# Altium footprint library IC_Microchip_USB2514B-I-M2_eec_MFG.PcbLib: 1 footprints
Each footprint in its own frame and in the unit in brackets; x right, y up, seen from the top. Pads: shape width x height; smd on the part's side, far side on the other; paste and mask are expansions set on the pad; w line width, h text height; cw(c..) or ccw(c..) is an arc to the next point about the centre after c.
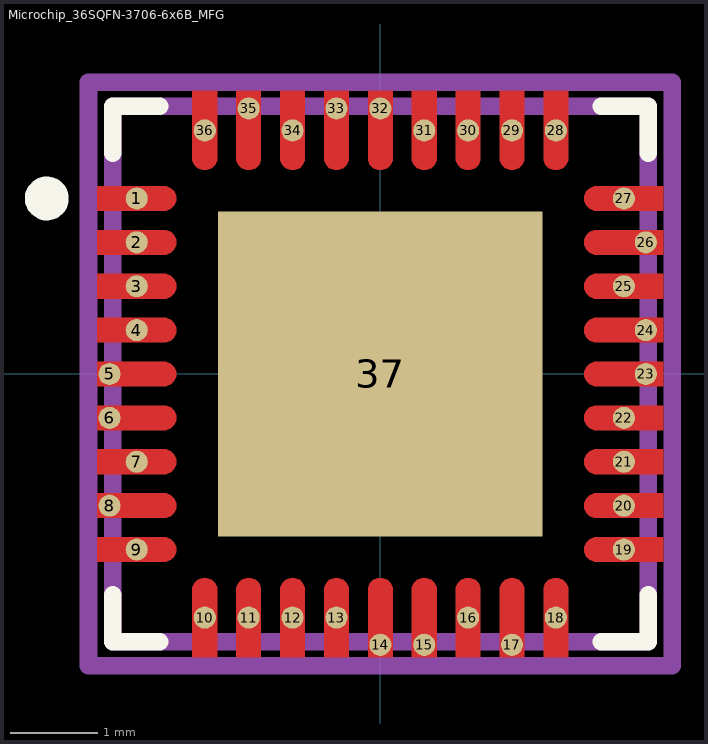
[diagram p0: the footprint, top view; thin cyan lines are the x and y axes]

## Microchip_36SQFN-3706-6x6B_MFG [mm]
pads (37):
  round 0.252 smd paste+0 mask+0: 1(-2.775,2) 2(-2.775,1.5) 3(-2.775,1) 4(-2.775,0.5) 5(-3.085,0) 6(-3.085,-0.5) 7(-2.775,-1) 8(-3.085,-1.5) 9(-2.775,-2) 10(-2,-2.775) 11(-1.5,-2.775) 12(-1,-2.775) 13(-0.5,-2.775) 14(0,-3.085) 15(0.5,-3.085) 16(1,-2.775) 17(1.5,-3.085) 18(2,-2.775) 19(2.775,-2) 20(2.775,-1.5) 21(2.775,-1) 22(2.775,-0.5) 23(3.025,0) 24(3.025,0.5) 25(2.775,1) 26(3.025,1.5) 27(2.775,2) 28(2,2.775) 29(1.5,2.775) 30(1,2.775) 31(0.5,2.775) 32(0,3.025) 33(-0.5,3.025) 34(-1,2.775) 35(-1.5,3.025) 36(-2,2.775)
  rect 3.7x3.7 smd paste+0 mask+0: 37(0,0)
Top Layer:
  region: -3.225,2.14 -2.465,2.14 -2.437,2.14 -2.386,2.119 -2.346,2.079 -2.325,2.028 -2.325,2 -2.325,1.972 -2.346,1.921 -2.386,1.881 -2.437,1.86 -2.465,1.86 -3.225,1.86
  region: -3.225,1.64 -2.465,1.64 -2.437,1.64 -2.386,1.619 -2.346,1.579 -2.325,1.528 -2.325,1.5 -2.325,1.472 -2.346,1.421 -2.386,1.381 -2.437,1.36 -2.465,1.36 -3.225,1.36
  region: -3.225,1.14 -2.465,1.14 -2.437,1.14 -2.386,1.119 -2.346,1.079 -2.325,1.028 -2.325,1 -2.325,0.972 -2.346,0.921 -2.386,0.881 -2.437,0.86 -2.465,0.86 -3.225,0.86
  region: -3.225,0.64 -2.465,0.64 -2.437,0.64 -2.386,0.619 -2.346,0.579 -2.325,0.528 -2.325,0.5 -2.325,0.472 -2.346,0.421 -2.386,0.381 -2.437,0.36 -2.465,0.36 -3.225,0.36
  region: -3.225,0.14 -2.465,0.14 -2.437,0.14 -2.386,0.119 -2.346,0.079 -2.325,0.028 -2.325,0 -2.325,-0.028 -2.346,-0.079 -2.386,-0.119 -2.437,-0.14 -2.465,-0.14 -3.225,-0.14
  region: -3.225,-0.36 -2.465,-0.36 -2.437,-0.36 -2.386,-0.381 -2.346,-0.421 -2.325,-0.472 -2.325,-0.5 -2.325,-0.528 -2.346,-0.579 -2.386,-0.619 -2.437,-0.64 -2.465,-0.64 -3.225,-0.64
  region: -3.225,-0.86 -2.465,-0.86 -2.437,-0.86 -2.386,-0.881 -2.346,-0.921 -2.325,-0.972 -2.325,-1 -2.325,-1.028 -2.346,-1.079 -2.386,-1.119 -2.437,-1.14 -2.465,-1.14 -3.225,-1.14
  region: -3.225,-1.36 -2.465,-1.36 -2.437,-1.36 -2.386,-1.381 -2.346,-1.421 -2.325,-1.472 -2.325,-1.5 -2.325,-1.528 -2.346,-1.579 -2.386,-1.619 -2.437,-1.64 -2.465,-1.64 -3.225,-1.64
  region: -3.225,-1.86 -2.465,-1.86 -2.437,-1.86 -2.386,-1.881 -2.346,-1.921 -2.325,-1.972 -2.325,-2 -2.325,-2.028 -2.346,-2.079 -2.386,-2.119 -2.437,-2.14 -2.465,-2.14 -3.225,-2.14
  region: 3.225,-2.14 2.465,-2.14 2.437,-2.14 2.386,-2.119 2.346,-2.079 2.325,-2.028 2.325,-2 2.325,-1.972 2.346,-1.921 2.386,-1.881 2.437,-1.86 2.465,-1.86 3.225,-1.86
  region: 3.225,-1.64 2.465,-1.64 2.437,-1.64 2.386,-1.619 2.346,-1.579 2.325,-1.528 2.325,-1.5 2.325,-1.472 2.346,-1.421 2.386,-1.381 2.437,-1.36 2.465,-1.36 3.225,-1.36
  region: 3.225,-1.14 2.465,-1.14 2.437,-1.14 2.386,-1.119 2.346,-1.079 2.325,-1.028 2.325,-1 2.325,-0.972 2.346,-0.921 2.386,-0.881 2.437,-0.86 2.465,-0.86 3.225,-0.86
  region: 3.225,-0.64 2.465,-0.64 2.437,-0.64 2.386,-0.619 2.346,-0.579 2.325,-0.528 2.325,-0.5 2.325,-0.472 2.346,-0.421 2.386,-0.381 2.437,-0.36 2.465,-0.36 3.225,-0.36
  region: 3.225,-0.14 2.465,-0.14 2.437,-0.14 2.386,-0.119 2.346,-0.079 2.325,-0.028 2.325,0 2.325,0.028 2.346,0.079 2.386,0.119 2.437,0.14 2.465,0.14 3.225,0.14
  region: 3.225,0.36 2.465,0.36 2.437,0.36 2.386,0.381 2.346,0.421 2.325,0.472 2.325,0.5 2.325,0.528 2.346,0.579 2.386,0.619 2.437,0.64 2.465,0.64 3.225,0.64
  region: 3.225,0.86 2.465,0.86 2.437,0.86 2.386,0.881 2.346,0.921 2.325,0.972 2.325,1 2.325,1.028 2.346,1.079 2.386,1.119 2.437,1.14 2.465,1.14 3.225,1.14
  region: 3.225,1.36 2.465,1.36 2.437,1.36 2.386,1.381 2.346,1.421 2.325,1.472 2.325,1.5 2.325,1.528 2.346,1.579 2.386,1.619 2.437,1.64 2.465,1.64 3.225,1.64
  region: 3.225,1.86 2.465,1.86 2.437,1.86 2.386,1.881 2.346,1.921 2.325,1.972 2.325,2 2.325,2.028 2.346,2.079 2.386,2.119 2.437,2.14 2.465,2.14 3.225,2.14
  region: -2.14,-3.225 -2.14,-2.465 -2.14,-2.437 -2.119,-2.386 -2.079,-2.346 -2.028,-2.325 -2,-2.325 -1.972,-2.325 -1.921,-2.346 -1.881,-2.386 -1.86,-2.437 -1.86,-2.465 -1.86,-3.225
  region: -1.64,-3.225 -1.64,-2.465 -1.64,-2.437 -1.619,-2.386 -1.579,-2.346 -1.528,-2.325 -1.5,-2.325 -1.472,-2.325 -1.421,-2.346 -1.381,-2.386 -1.36,-2.437 -1.36,-2.465 -1.36,-3.225
  region: -1.14,-3.225 -1.14,-2.465 -1.14,-2.437 -1.119,-2.386 -1.079,-2.346 -1.028,-2.325 -1,-2.325 -0.972,-2.325 -0.921,-2.346 -0.881,-2.386 -0.86,-2.437 -0.86,-2.465 -0.86,-3.225
  region: -0.64,-3.225 -0.64,-2.465 -0.64,-2.437 -0.619,-2.386 -0.579,-2.346 -0.528,-2.325 -0.5,-2.325 -0.472,-2.325 -0.421,-2.346 -0.381,-2.386 -0.36,-2.437 -0.36,-2.465 -0.36,-3.225
  region: -0.14,-3.225 -0.14,-2.465 -0.14,-2.437 -0.119,-2.386 -0.079,-2.346 -0.028,-2.325 0,-2.325 0.028,-2.325 0.079,-2.346 0.119,-2.386 0.14,-2.437 0.14,-2.465 0.14,-3.225
  region: 0.36,-3.225 0.36,-2.465 0.36,-2.437 0.381,-2.386 0.421,-2.346 0.472,-2.325 0.5,-2.325 0.528,-2.325 0.579,-2.346 0.619,-2.386 0.64,-2.437 0.64,-2.465 0.64,-3.225
  region: 0.86,-3.225 0.86,-2.465 0.86,-2.437 0.881,-2.386 0.921,-2.346 0.972,-2.325 1,-2.325 1.028,-2.325 1.079,-2.346 1.119,-2.386 1.14,-2.437 1.14,-2.465 1.14,-3.225
  region: 1.36,-3.225 1.36,-2.465 1.36,-2.437 1.381,-2.386 1.421,-2.346 1.472,-2.325 1.5,-2.325 1.528,-2.325 1.579,-2.346 1.619,-2.386 1.64,-2.437 1.64,-2.465 1.64,-3.225
  region: 1.86,-3.225 1.86,-2.465 1.86,-2.437 1.881,-2.386 1.921,-2.346 1.972,-2.325 2,-2.325 2.028,-2.325 2.079,-2.346 2.119,-2.386 2.14,-2.437 2.14,-2.465 2.14,-3.225
  region: 2.14,3.225 2.14,2.465 2.14,2.437 2.119,2.386 2.079,2.346 2.028,2.325 2,2.325 1.972,2.325 1.921,2.346 1.881,2.386 1.86,2.437 1.86,2.465 1.86,3.225
  region: 1.64,3.225 1.64,2.465 1.64,2.437 1.619,2.386 1.579,2.346 1.528,2.325 1.5,2.325 1.472,2.325 1.421,2.346 1.381,2.386 1.36,2.437 1.36,2.465 1.36,3.225
  region: 1.14,3.225 1.14,2.465 1.14,2.437 1.119,2.386 1.079,2.346 1.028,2.325 1,2.325 0.972,2.325 0.921,2.346 0.881,2.386 0.86,2.437 0.86,2.465 0.86,3.225
  region: 0.64,3.225 0.64,2.465 0.64,2.437 0.619,2.386 0.579,2.346 0.528,2.325 0.5,2.325 0.472,2.325 0.421,2.346 0.381,2.386 0.36,2.437 0.36,2.465 0.36,3.225
  region: 0.14,3.225 0.14,2.465 0.14,2.437 0.119,2.386 0.079,2.346 0.028,2.325 0,2.325 -0.028,2.325 -0.079,2.346 -0.119,2.386 -0.14,2.437 -0.14,2.465 -0.14,3.225
  region: -0.36,3.225 -0.36,2.465 -0.36,2.437 -0.381,2.386 -0.421,2.346 -0.472,2.325 -0.5,2.325 -0.528,2.325 -0.579,2.346 -0.619,2.386 -0.64,2.437 -0.64,2.465 -0.64,3.225
  region: -0.86,3.225 -0.86,2.465 -0.86,2.437 -0.881,2.386 -0.921,2.346 -0.972,2.325 -1,2.325 -1.028,2.325 -1.079,2.346 -1.119,2.386 -1.14,2.437 -1.14,2.465 -1.14,3.225
  region: -1.36,3.225 -1.36,2.465 -1.36,2.437 -1.381,2.386 -1.421,2.346 -1.472,2.325 -1.5,2.325 -1.528,2.325 -1.579,2.346 -1.619,2.386 -1.64,2.437 -1.64,2.465 -1.64,3.225
  region: -1.86,3.225 -1.86,2.465 -1.86,2.437 -1.881,2.386 -1.921,2.346 -1.972,2.325 -2,2.325 -2.028,2.325 -2.079,2.346 -2.119,2.386 -2.14,2.437 -2.14,2.465 -2.14,3.225
Top Overlay:
  circle w0.25: c-3.8,2 r0.125
  lines w0.2: -3.05,-2.515 -3.05,-3.05 -2.515,-3.05 ; -3.05,2.515 -3.05,3.05 -2.515,3.05 ; 2.515,-3.05 3.05,-3.05 3.05,-2.515 ; 2.515,3.05 3.05,3.05 3.05,2.515
Mechanical 10:
  lines w0.2: -3.325,-3.325 3.325,-3.325 3.325,3.325 -3.325,3.325 -3.325,-3.325
  text ".Designator" at 0,0.188 h1
Mechanical 12:
  lines w0.2: -3.05,-3.05 3.05,-3.05 3.05,3.05 -3.05,3.05 -3.05,-3.05
Mechanical 15:
  lines w0.1: -0.5,0 0.5,0 ; 0,-0.5 0,0.5
  lines w0.2: -3.325,-3.325 3.325,-3.325 3.325,3.325 -3.325,3.325 -3.325,-3.325
3D body "IC_Microchip_USB2514B-I-M2_eec.STEP": height 0.25, standoff 0, extent -3.325,-3.325 3.325,3.325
